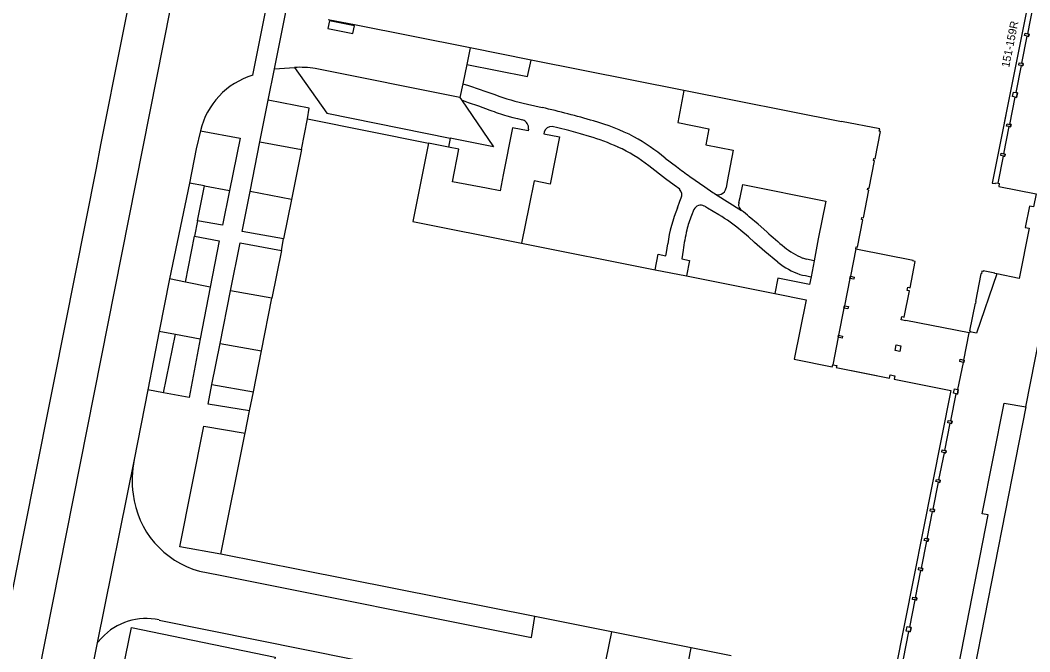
# Model space of a CAD drawing. Extents: x 158797 to 159887, y 384318 to 385255.
# Drawn here: x 159499.6 to 159625.7, y 384558.1 to 384637 of the extents above; entities that cross this region are included whole.
import ezdxf

# ---------------------------------------------------------------- set-up
doc = ezdxf.new("R2010")
doc.units = 0
for name, color, linetype in [('IMGEO_Groenvoorziening', 7, 'Continuous'), ('IMGEO_Lage_trafo', 7, 'Continuous'), ('IMGEO_Pand', 7, 'Continuous'), ('IMGEO_Pand_nummerreeks', 7, 'Continuous'), ('IMGEO_Pand_overbouw', 7, 'Continuous'), ('IMGEO_Parkeervlak_halfverhard', 7, 'Continuous'), ('IMGEO_Parkeervlak_open', 7, 'Continuous'), ('IMGEO_Rijbaan_lokaal_gesloten', 7, 'Continuous'), ('IMGEO_Voetpad_open', 7, 'Continuous')]:
    doc.layers.add(name, color=color, linetype=linetype)

msp = doc.modelspace()

# ---------------------------------------------------------------- linework, layer by layer
at = {"layer": 'IMGEO_Groenvoorziening'}
msp.add_lwpolyline([(159553.32, 384622.28), (159553.09, 384621.17)], dxfattribs=at)
at = {"layer": 'IMGEO_Lage_trafo'}
msp.add_lwpolyline([(159538.03, 384635.97), (159541.15, 384635.35), (159541.34, 384636.33), (159538.23, 384636.95), (159538.03, 384635.97)], dxfattribs=at)
at = {"layer": 'IMGEO_Pand'}
for points in [[(159618.06, 384679.12), (159625.23, 384677.72), (159625.27, 384677.94), (159625.86, 384677.83), (159625.81, 384677.6), (159632.89, 384676.19), (159621.3, 384617.93), (159621.05, 384616.68), (159621.42, 384616.6), (159621.45, 384616.72), (159621.77, 384616.66), (159621.93, 384616.62), (159621.86, 384616.25), (159626.52, 384615.32), (159626.2, 384613.71), (159625.7, 384613.81), (159625.17, 384611.14), (159625.67, 384611.04), (159624.42, 384604.76), (159621.61, 384605.32)], [(159519.58, 384671.66), (159515.47, 384650.93), (159514.85, 384647.81), (159509.62, 384621.45), (159509.05, 384618.53), (159503.78, 384591.95), (159503.2, 384589.03), (159500, 384572.9), (159497.97, 384562.69), (159497.36, 384559.59), (159487.6, 384510.37), (159488.07, 384510.28), (159487.96, 384509.7), (159487.49, 384509.79), (159487.42, 384509.45), (159487.14, 384509.51)], [(159555.81, 384633.55), (159541.36, 384636.42), (159538.25, 384637.04), (159538.05, 384637.08)], [(159625.16, 384635.39), (159625.48, 384635.32), (159625.65, 384635.29), (159625.59, 384635), (159625.43, 384635.04), (159625.1, 384635.1), (159625.16, 384635.39)], [(159563.41, 384632.04), (159555.81, 384633.55)], [(159582.49, 384628.24), (159563.41, 384632.04)], [(159624.43, 384631.71), (159624.75, 384631.64), (159624.92, 384631.61), (159624.86, 384631.33), (159624.69, 384631.36), (159624.37, 384631.42), (159624.43, 384631.71)], [(159618.25, 384598.09), (159618.22, 384597.97), (159618.17, 384597.98), (159610.27, 384599.53), (159610.26, 384599.48), (159609.68, 384599.6), (159609.75, 384599.99), (159610.05, 384599.93), (159610.71, 384603.21), (159610.41, 384603.27), (159610.49, 384603.67), (159610.78, 384603.61), (159611.43, 384606.89), (159611.14, 384606.95), (159611.15, 384607.01), (159604.22, 384608.38), (159604.22, 384608.4), (159603.99, 384608.45), (159604.04, 384608.7), (159604.21, 384608.66), (159604.89, 384612.1), (159604.73, 384612.13), (159604.77, 384612.37), (159604.94, 384612.34), (159605.62, 384615.77), (159605.46, 384615.81), (159605.51, 384616.05), (159605.67, 384616.02), (159606.35, 384619.45), (159606.19, 384619.48), (159606.24, 384619.73), (159606.4, 384619.7), (159607.08, 384623.13), (159606.92, 384623.16), (159606.98, 384623.43), (159602.21, 384624.38), (159602.2, 384624.32), (159582.49, 384628.24)], [(159623.7, 384628.03), (159624.02, 384627.97), (159624.19, 384627.93), (159624.08, 384627.37), (159623.91, 384627.41), (159623.58, 384627.47), (159623.7, 384628.03)], [(159534.71, 384620.87), (159535.46, 384624.68)], [(159535.46, 384624.68), (159550.59, 384621.67)], [(159622.91, 384624.08), (159623.23, 384624.01), (159623.4, 384623.98), (159623.34, 384623.7), (159623.18, 384623.73), (159622.85, 384623.79), (159622.91, 384624.08)], [(159550.59, 384621.67), (159548.64, 384611.87), (159562.23, 384609.17)], [(159534.71, 384620.87), (159533.47, 384614.62)], [(159622.18, 384620.4), (159622.5, 384620.34), (159622.67, 384620.3), (159622.61, 384620.02), (159622.44, 384620.05), (159622.12, 384620.12), (159622.18, 384620.4)], [(159533.47, 384614.62), (159532.49, 384609.7)], [(159532.21, 384608.24), (159532.49, 384609.7)], [(159562.23, 384609.17), (159578.92, 384605.85)], [(159532.21, 384608.24), (159531.03, 384602.3)], [(159578.92, 384605.85), (159582.84, 384605.07)], [(159582.84, 384605.07), (159593.86, 384602.88)], [(159603.32, 384605.04), (159603.8, 384604.94), (159603.75, 384604.66), (159603.26, 384604.75), (159603.32, 384605.04)], [(159621.61, 384605.32), (159621.38, 384605.36), (159621.39, 384605.42), (159619.93, 384605.71), (159619.91, 384605.65), (159619.76, 384605.68), (159619.69, 384605.33), (159619.64, 384605.34), (159618.95, 384601.9), (159619, 384601.89), (159618.95, 384601.65), (159618.9, 384601.66), (159618.22, 384598.23), (159618.27, 384598.22), (159618.25, 384598.09)], [(159529.73, 384595.72), (159531.03, 384602.3)], [(159593.86, 384602.88), (159597.78, 384602.1), (159596.3, 384594.68), (159601.06, 384593.73), (159601.11, 384593.98), (159601.61, 384593.89), (159601.55, 384593.63), (159608.22, 384592.3), (159608.3, 384592.71), (159608.89, 384592.59), (159608.81, 384592.19), (159615.89, 384590.78), (159607.76, 384549.9), (159608.13, 384549.83), (159608.16, 384549.97), (159608.42, 384549.92), (159608.41, 384549.9), (159608.48, 384549.89), (159608.64, 384549.85), (159608.6, 384549.61), (159608.68, 384549.59), (159608.17, 384547.04)], [(159602.58, 384601.34), (159603.07, 384601.24), (159603.01, 384600.96), (159602.52, 384601.05), (159602.58, 384601.34)], [(159601.85, 384597.66), (159602.34, 384597.56), (159602.29, 384597.32), (159601.8, 384597.42), (159601.85, 384597.66)], [(159609.05, 384596.48), (159609.64, 384596.36), (159609.5, 384595.63), (159608.91, 384595.75), (159609.05, 384596.48)], [(159528.71, 384590.6), (159529.73, 384595.72)], [(159617.05, 384594.66), (159617.49, 384594.57), (159617.54, 384594.56), (159617.49, 384594.27), (159617.44, 384594.28), (159617, 384594.37), (159617.05, 384594.66)], [(159616.32, 384590.98), (159616.76, 384590.89), (159616.81, 384590.88), (159616.7, 384590.32), (159616.53, 384590.35), (159616.21, 384590.42), (159616.32, 384590.98)], [(159528.24, 384588.22), (159528.71, 384590.6)], [(159527.69, 384585.43), (159528.24, 384588.22)], [(159615.53, 384587.02), (159615.86, 384586.96), (159616.02, 384586.93), (159615.97, 384586.64), (159615.8, 384586.68), (159615.48, 384586.74), (159615.53, 384587.02)], [(159524.65, 384570.31), (159527.63, 384585.28), (159527.66, 384585.27), (159527.69, 384585.43)], [(159614.8, 384583.35), (159615.12, 384583.28), (159615.29, 384583.25), (159615.24, 384582.97), (159615.07, 384583), (159614.74, 384583.06), (159614.8, 384583.35)], [(159614.07, 384579.67), (159614.39, 384579.6), (159614.56, 384579.57), (159614.5, 384579.29), (159614.34, 384579.32), (159614.01, 384579.39), (159614.07, 384579.67)], [(159613.34, 384575.99), (159613.66, 384575.93), (159613.83, 384575.89), (159613.77, 384575.61), (159613.6, 384575.64), (159613.28, 384575.71), (159613.34, 384575.99)], [(159612.61, 384572.31), (159612.93, 384572.25), (159613.1, 384572.22), (159613.04, 384571.93), (159612.87, 384571.97), (159612.55, 384572.03), (159612.61, 384572.31)], [(159563.9, 384562.52), (159534.71, 384568.33), (159534.71, 384568.31), (159524.65, 384570.31)], [(159611.87, 384568.64), (159612.2, 384568.57), (159612.36, 384568.54), (159612.31, 384568.25), (159612.14, 384568.29), (159611.82, 384568.35), (159611.87, 384568.64)], [(159611.14, 384564.96), (159611.46, 384564.89), (159611.63, 384564.86), (159611.58, 384564.58), (159611.41, 384564.61), (159611.08, 384564.67), (159611.14, 384564.96)], [(159573.47, 384560.62), (159563.9, 384562.52)], [(159583.43, 384558.63), (159573.47, 384560.62)], [(159610.41, 384561.28), (159610.73, 384561.22), (159610.9, 384561.18), (159610.79, 384560.62), (159610.62, 384560.66), (159610.3, 384560.72), (159610.41, 384561.28)], [(159588.44, 384557.64), (159583.43, 384558.63)]]:
    msp.add_lwpolyline(points, dxfattribs=at)
at = {"layer": 'IMGEO_Pand_overbouw'}
for points in [[(159632.89, 384676.19), (159621.05, 384616.68), (159621.42, 384616.6), (159621.45, 384616.72), (159621.77, 384616.66), (159622.44, 384620.05), (159622.61, 384620.02), (159622.67, 384620.3), (159622.5, 384620.34), (159623.18, 384623.73), (159623.34, 384623.7), (159623.4, 384623.98), (159623.23, 384624.01), (159623.91, 384627.41), (159624.08, 384627.37), (159624.19, 384627.93), (159624.02, 384627.97), (159624.69, 384631.36), (159624.86, 384631.33), (159624.92, 384631.61), (159624.75, 384631.64), (159625.43, 384635.04), (159625.59, 384635), (159625.65, 384635.29), (159625.48, 384635.32), (159626.16, 384638.72)], [(159609.95, 384557.26), (159610.62, 384560.66), (159610.79, 384560.62), (159610.9, 384561.18), (159610.73, 384561.22), (159611.41, 384564.61), (159611.58, 384564.58), (159611.63, 384564.86), (159611.46, 384564.89), (159612.14, 384568.29), (159612.31, 384568.25), (159612.36, 384568.54), (159612.2, 384568.57), (159612.87, 384571.97), (159613.04, 384571.93), (159613.1, 384572.22), (159612.93, 384572.25), (159613.6, 384575.64), (159613.77, 384575.61), (159613.83, 384575.89), (159613.66, 384575.93), (159614.34, 384579.32), (159614.5, 384579.29), (159614.56, 384579.57), (159614.39, 384579.6), (159615.07, 384583), (159615.24, 384582.97), (159615.29, 384583.25), (159615.12, 384583.28), (159615.8, 384586.68), (159615.97, 384586.64), (159616.02, 384586.93), (159615.86, 384586.96), (159616.53, 384590.35), (159616.7, 384590.32), (159616.81, 384590.88), (159616.76, 384590.89), (159617.44, 384594.28), (159617.49, 384594.27), (159617.54, 384594.56), (159617.49, 384594.57), (159618.17, 384597.98), (159610.27, 384599.53), (159610.26, 384599.48), (159609.68, 384599.6), (159609.75, 384599.99), (159610.05, 384599.93), (159610.71, 384603.21), (159610.41, 384603.27), (159610.49, 384603.67), (159610.78, 384603.61), (159611.43, 384606.89), (159611.14, 384606.95), (159611.15, 384607.01), (159604.22, 384608.38), (159604.22, 384608.4), (159603.99, 384608.45), (159603.32, 384605.04), (159603.26, 384604.75), (159602.58, 384601.34), (159602.52, 384601.05), (159601.85, 384597.66), (159601.8, 384597.42), (159601.11, 384593.98), (159601.61, 384593.89), (159601.55, 384593.63), (159605.13, 384592.92), (159608.22, 384592.3), (159608.3, 384592.71), (159608.89, 384592.59), (159608.81, 384592.19), (159615.89, 384590.78), (159607.76, 384549.9)]]:
    msp.add_lwpolyline(points, dxfattribs=at)
at = {"layer": 'IMGEO_Parkeervlak_halfverhard'}
for points in [[(159533.86, 384631.12), (159537.9, 384625.39), (159553.32, 384622.28)], [(159535.46, 384624.68), (159535.7, 384626.03), (159530.56, 384627.01)], [(159554.72, 384627.06), (159558.71, 384621.2), (159553.32, 384622.28)], [(159523.54, 384591.52), (159528.71, 384590.6)]]:
    msp.add_lwpolyline(points, dxfattribs=at)
at = {"layer": 'IMGEO_Parkeervlak_open'}
for points in [[(159521.73, 384611.97), (159522.62, 384616.33)], [(159520.24, 384604.3), (159521.35, 384610.04)], [(159517.49, 384590.49), (159518.97, 384597.81)]]:
    msp.add_lwpolyline(points, dxfattribs=at)
at = {"layer": 'IMGEO_Rijbaan_lokaal_gesloten'}
for points in [[(159487.93, 384485.21), (159527.95, 384686.82)], [(159530.47, 384639.54), (159528.62, 384630.15)], [(159531.35, 384630.95), (159532.79, 384638.04)], [(159555.81, 384633.55), (159555.38, 384631.48)], [(159555.38, 384631.48), (159554.88, 384629.07)], [(159531.35, 384630.95), (159533.86, 384631.12)], [(159554.52, 384627.35), (159536.45, 384630.99)], [(159554.88, 384629.07), (159554.52, 384627.35)], [(159522.09, 384623.19), (159521.56, 384620.96), (159520.72, 384616.67)], [(159522.09, 384623.19), (159527.06, 384622.28), (159525.74, 384615.74)], [(159528.31, 384615.62), (159529.54, 384621.83)], [(159529.54, 384621.83), (159534.71, 384620.87)], [(159625.25, 384588.73), (159630.97, 384617.68), (159631.86, 384622.18)], [(159520.72, 384616.67), (159518.22, 384604.7)], [(159522.62, 384616.33), (159520.72, 384616.67)], [(159522.62, 384616.33), (159525.74, 384615.74)], [(159533.47, 384614.62), (159528.31, 384615.62)], [(159518.22, 384604.7), (159516.95, 384598.19)], [(159520.24, 384604.3), (159518.22, 384604.7)], [(159523.33, 384603.68), (159520.24, 384604.3)], [(159523.33, 384603.68), (159522.07, 384597.22)], [(159524.56, 384596.65), (159525.86, 384603.23)], [(159531.03, 384602.3), (159525.86, 384603.23)], [(159516.95, 384598.19), (159515.52, 384590.85)], [(159516.95, 384598.19), (159518.97, 384597.81)], [(159518.97, 384597.81), (159522.07, 384597.22)], [(159524.56, 384596.65), (159529.73, 384595.72)], [(159515.52, 384590.85), (159513.8, 384582.14)], [(159625.25, 384588.73), (159617.51, 384549.27)], [(159513.8, 384582.14), (159509.18, 384559.24)], [(159521.97, 384568.2), (159524.37, 384567.73), (159563.46, 384559.92), (159563.9, 384562.52)], [(159516.94, 384562.1), (159547.37, 384555.96), (159551.38, 384555.15), (159553.62, 384554.38)], [(159573.47, 384560.62), (159570.89, 384547.99)], [(159509.18, 384559.24), (159509.76, 384559.86)], [(159509.18, 384559.24), (159504.75, 384536.86)], [(159580.96, 384546.07), (159583.43, 384558.63)]]:
    msp.add_lwpolyline(points, dxfattribs=at)
for centre, radius, start, end in [((159531.47, 384620.93), 9.65, 107.1259, 166.4401), ((159534.41, 384616.18), 14.95, 82.1701, 92.1338), ((159527.05, 384579.58), 13.49, 169.062, 187.4247), ((159524.99, 384579.2), 11.4, 186.8733, 254.6567), ((159515.29, 384554.77), 7.52, 77.3156, 137.367)]:
    msp.add_arc(centre, radius, start, end, dxfattribs=at)
at = {"layer": 'IMGEO_Voetpad_open'}
for points in [[(159555.38, 384631.48), (159562.99, 384629.97), (159563.41, 384632.04)], [(159530.56, 384627.01), (159531.35, 384630.95)], [(159554.88, 384629.07), (159555.61, 384628.87), (159557.07, 384628.37), (159557.51, 384628.21), (159558.88, 384627.72)], [(159582.49, 384628.24), (159581.74, 384624.23), (159585.65, 384623.45), (159585.25, 384621.47), (159588.68, 384620.8), (159587.94, 384616.89), (159587.78, 384616.08)], [(159529.54, 384621.83), (159530.56, 384627.01)], [(159554.52, 384627.35), (159554.72, 384627.06)], [(159554.72, 384627.06), (159555.57, 384626.75), (159556.84, 384626.31), (159558.26, 384625.77)], [(159562.95, 384626.52), (159564.81, 384626.11)], [(159560.38, 384625.08), (159561.14, 384624.87), (159561.71, 384624.72), (159562.36, 384624.56)], [(159570.7, 384622.49), (159569.59, 384622.82), (159568.14, 384623.22), (159566.75, 384623.58), (159566.04, 384623.75)], [(159563.1, 384623.39), (159563.06, 384623.19), (159561.11, 384623.58), (159559.93, 384617.71), (159559.54, 384615.72), (159557.83, 384616.03), (159553.58, 384616.84), (159554.4, 384620.91), (159553.09, 384621.17)], [(159565.05, 384623.02), (159565.01, 384622.81), (159566.95, 384622.43), (159565.81, 384616.54), (159563.8, 384616.94), (159563.17, 384613.88), (159562.23, 384609.17)], [(159553.09, 384621.17), (159550.59, 384621.67)], [(159581.99, 384615.9), (159581.31, 384616.4), (159580.23, 384617.21), (159578.12, 384618.84)], [(159580.19, 384619.8), (159581.59, 384618.73)], [(159583.26, 384617.5), (159585.14, 384616.2), (159586.13, 384615.5), (159586.29, 384615.4), (159586.47, 384615.3)], [(159589.39, 384614.23), (159589.53, 384614.87), (159589.88, 384616.5), (159600.25, 384614.41), (159599.31, 384609.71), (159598.78, 384606.98)], [(159525.74, 384615.74), (159524.85, 384611.4), (159521.73, 384611.97)], [(159532.49, 384609.7), (159527.32, 384610.61), (159528.31, 384615.62)], [(159581.71, 384613.58), (159582.02, 384614.4), (159582.18, 384614.81)], [(159586.47, 384615.3), (159589.71, 384613.25)], [(159586.87, 384612.7), (159585.48, 384613.56), (159585.07, 384613.81)], [(159583.77, 384613.36), (159583.48, 384612.61)], [(159592.88, 384610.59), (159591.8, 384611.53), (159590.69, 384612.47)], [(159521.73, 384611.97), (159521.35, 384610.04)], [(159521.35, 384610.04), (159524.45, 384609.45), (159523.33, 384603.68)], [(159594.27, 384606.78), (159592.62, 384608.11), (159591.34, 384609.24), (159590.58, 384609.94), (159589.64, 384610.74)], [(159525.86, 384603.23), (159527.05, 384609.23), (159532.21, 384608.24)], [(159578.92, 384605.85), (159579.31, 384607.79), (159580.26, 384607.6), (159580.34, 384608.01), (159580.49, 384609.1)], [(159582.43, 384608.29), (159582.26, 384607.2), (159583.23, 384607.01), (159582.84, 384605.07)], [(159598.78, 384606.98), (159597.84, 384607.17)], [(159598.78, 384606.98), (159598.4, 384604.97)], [(159598.4, 384604.97), (159598.22, 384604.02), (159594.24, 384604.8), (159593.86, 384602.88)], [(159621.61, 384605.32), (159619.1, 384597.92), (159618.25, 384598.09)], [(159522.07, 384597.22), (159520.68, 384589.88), (159517.49, 384590.49)], [(159523.54, 384591.52), (159524.56, 384596.65)], [(159517.49, 384590.49), (159515.52, 384590.85)], [(159528.24, 384588.22), (159523.06, 384589.08), (159523.54, 384591.52)], [(159617.51, 384549.27), (159615.53, 384549.62), (159620.52, 384575.22), (159619.8, 384575.35), (159622.54, 384589.17), (159625.25, 384588.73)], [(159524.65, 384570.31), (159519.53, 384571.25), (159522.52, 384586.32), (159527.69, 384585.43)], [(159511.87, 384506.01), (159502.59, 384507.88), (159513.48, 384561.15), (159531.42, 384557.48), (159530.86, 384554.5)]]:
    msp.add_lwpolyline(points, dxfattribs=at)
for centre, radius, start, end in [((159569.89, 384657.54), 31.78, 249.7303, 257.3932), ((159592.4, 384726.18), 106.05, 251.2234, 252.4272), ((159542.91, 384528.97), 99.57, 73.4811, 77.2982), ((159562.04, 384623.54), 1.07, 351.5095, 72.825), ((159566, 384622.78), 0.975, 87.351, 165.5125), ((159563.9, 384598.26), 27.18, 62.9241, 74.3646), ((159562.73, 384595.33), 28.31, 65.9178, 73.6354), ((159562.72, 384598.3), 27.7, 50.9063, 60.7135), ((159566.76, 384604.45), 18.33, 51.707, 65.7974), ((159599.84, 384641.7), 29.34, 231.5204, 235.5873), ((159586.83, 384616.2), 0.963, 289.8542, 352.7549), ((159581.26, 384615.21), 1, 336.5471, 43.7386), ((159586.82, 384616.02), 0.799, 243.9989, 295.0018), ((159598.78, 384606.52), 18.47, 157.5372, 171.985), ((159584.63, 384612.96), 0.95, 62.757, 154.8546), ((159590.09, 384613.99), 0.738, 160.806, 196.9425), ((159591.05, 384614.45), 1.81, 202.2216, 221.7297), ((159596.33, 384607.37), 13.89, 157.7949, 165.6404), ((159576.19, 384594.72), 20.92, 49.9656, 59.2881), ((159583.15, 384604.03), 11.32, 48.2362, 54.5869), ((159608.62, 384604.91), 26.41, 167.1024, 172.6451), ((159645.78, 384669.08), 78.87, 227.8699, 229.9909), ((159600.88, 384615.74), 9.14, 230.6123, 247.2296), ((159598.35, 384609.92), 2.79, 248.8517, 259.4708), ((159599.96, 384613.87), 9.09, 231.2304, 251.0968), ((159601.59, 384622.92), 18.23, 255.4569, 259.9069)]:
    msp.add_arc(centre, radius, start, end, dxfattribs=at)

# ---------------------------------------------------------------- texts
at = {"layer": 'IMGEO_Pand_nummerreeks'}
msp.add_text('151-159R', height=1, rotation=78.5468, dxfattribs=at).set_placement((159623.16, 384631.05))

doc.saveas('drawing.dxf')
